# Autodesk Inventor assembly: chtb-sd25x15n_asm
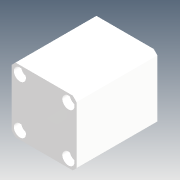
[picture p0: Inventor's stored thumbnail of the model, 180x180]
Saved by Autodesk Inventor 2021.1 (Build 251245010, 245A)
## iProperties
Company: Microsoft
Created: 2018-05
Part Number: chtb-sd25x15n_asm
Description: STEP AP214
Document SubType Name: Assembly
Designer: user
Title: chtb-sd25x15n_asm.STEP
Author: Windows
Revision Number: ÈÎºÎ
Sending System: SolidWorks 2015
Preprocessor: SwSTEP 2.0
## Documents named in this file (4)
- D:\Vault_2016\Projekty\Clamptek\Hydraulic\CHTB\CHTB-25\Inventor\chtb-sd25x15n\chtb-sd25x15n_asm.iam
- D:\Vault_2016\Projekty\Clamptek\Hydraulic\CHTB\CHTB-25\Inventor\chtb-sd25x15n\CHTB-25QG.ipt
- D:\Vault_2016\Projekty\Clamptek\Hydraulic\CHTB\CHTB-25\Inventor\chtb-sd25x15n\CHTB-SD25X15NBT.ipt
- D:\Vault_2016\Projekty\Clamptek\Hydraulic\CHTB\CHTB-25\Inventor\chtb-sd25x15n\CHTB-SD25X15NHSG.ipt
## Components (3 placed, 3 different names)
1. CHTB-25QG_1
2. CHTB-SD25X15NBT_2
3. CHTB-SD25X15NHSG_3
